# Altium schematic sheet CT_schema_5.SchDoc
size 422 x 414 mm
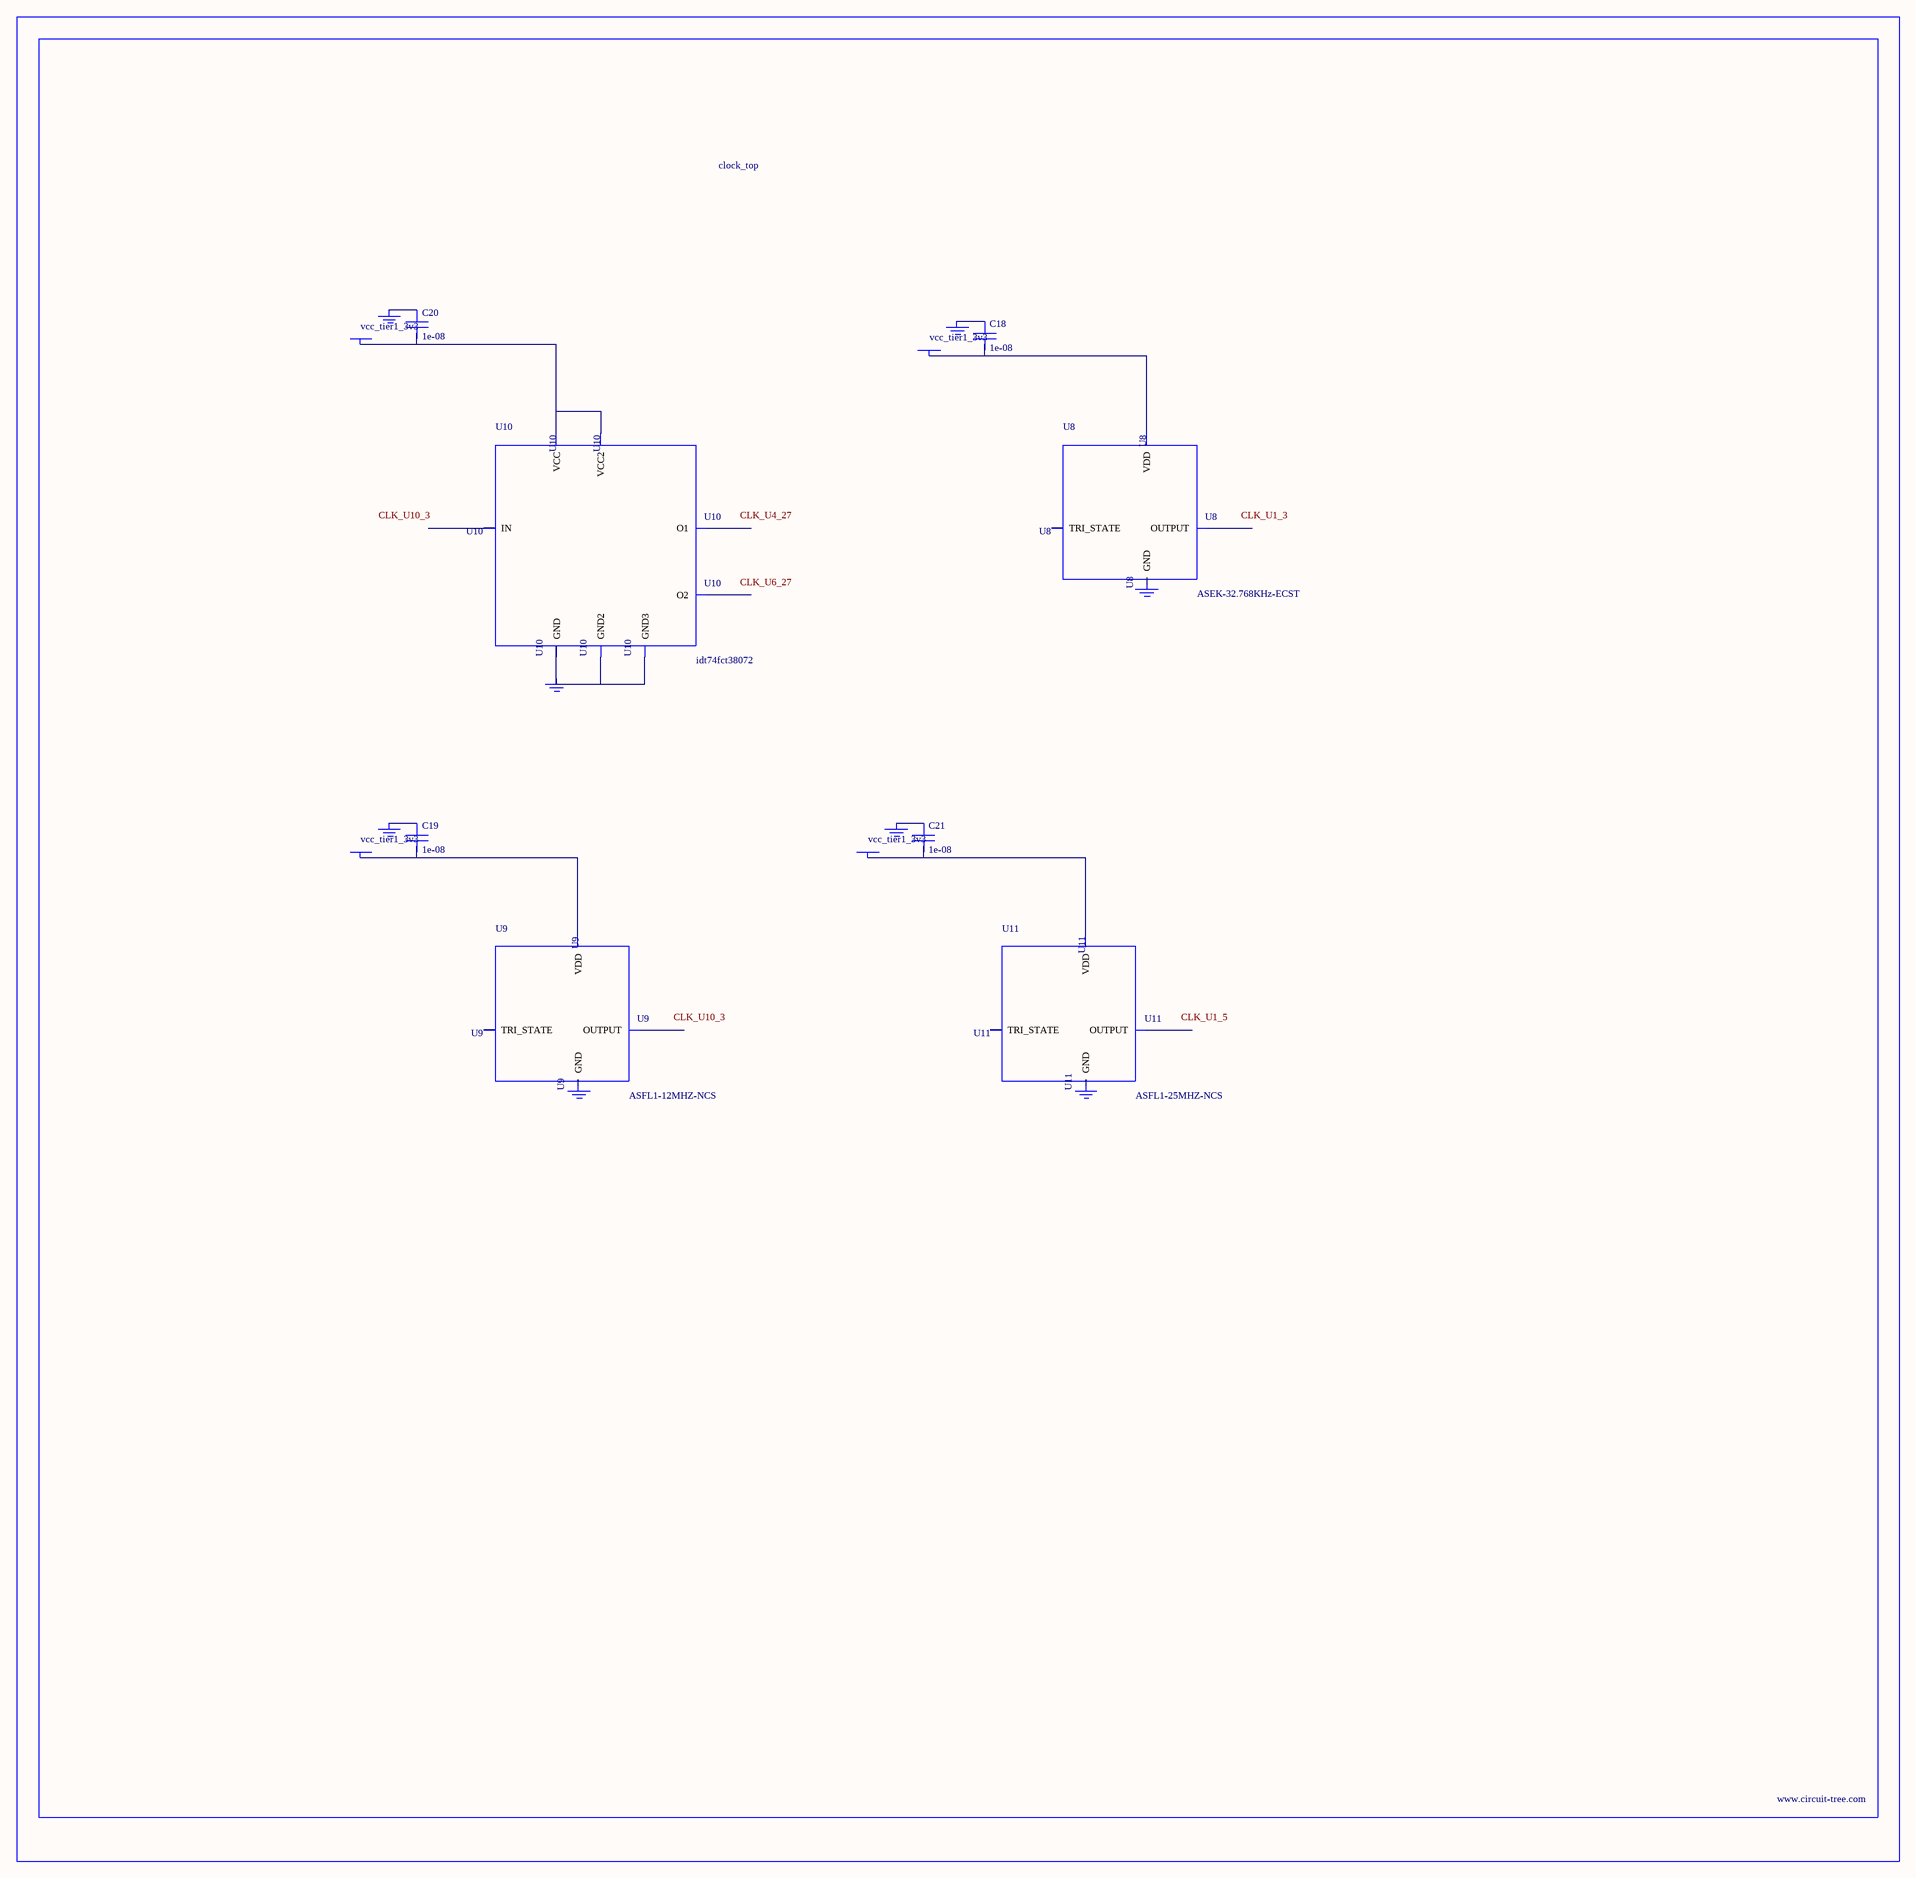
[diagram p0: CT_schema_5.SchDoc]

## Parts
BORDER4  (no value)
C18  1e-08  [C0402]
C19  1e-08  [C0402]
C20  1e-08  [C0402]
C21  1e-08  [C0402]
GND_INSTANCE_4_0  (no value)
GND_INSTANCE_4_1  (no value)
GND_INSTANCE_4_2  (no value)
GND_INSTANCE_4_3  (no value)
GND_INSTANCE_4_4  (no value)
GND_INSTANCE_4_5  (no value)
GND_INSTANCE_4_6  (no value)
GND_INSTANCE_4_7  (no value)
POWER_INSTANCE_4_0  vcc_tier1_3v3
POWER_INSTANCE_4_1  vcc_tier1_3v3
POWER_INSTANCE_4_2  vcc_tier1_3v3
POWER_INSTANCE_4_3  vcc_tier1_3v3
U8  ASEK-32.768KHz-ECST  [ASEK]
U9  ASFL1-12MHZ-NCS  [ASFL1]
U10  idt74fct38072  [IDT74FCT38072]
U11  ASFL1-25MHZ-NCS  [ASFL1]

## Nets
NetC18_1: C18.1 GND_INSTANCE_4_0.0(GND)
NetC18_2: C18.2 POWER_INSTANCE_4_0.0(PWR) U8.4(VDD)
NetC19_1: C19.1 GND_INSTANCE_4_2.0(GND)
NetC19_2: C19.2 POWER_INSTANCE_4_1.0(PWR) U9.4(VDD)
NetC20_1: C20.1 GND_INSTANCE_4_4.0(GND)
NetC20_2: C20.2 POWER_INSTANCE_4_2.0(PWR) U10.1(VCC) U10.2(VCC2)
NetC21_1: C21.1 GND_INSTANCE_4_6.0(GND)
NetC21_2: C21.2 POWER_INSTANCE_4_3.0(PWR) U11.4(VDD)
NetGND_INSTANCE_4_5_0: GND_INSTANCE_4_5.0(GND) U10.4(GND) U10.5(GND2) U10.8(GND3)

Not connected (* = marked no-connect by the designer): GND_INSTANCE_4_1 0(GND); GND_INSTANCE_4_3 0(GND); GND_INSTANCE_4_7 0(GND); U8 1(TRI_STATE) 2(GND) 3(OUTPUT); U9 1(TRI_STATE) 2(GND) 3(OUTPUT); U10 3(IN) 6(O2) 7(O1); U11 1(TRI_STATE) 2(GND) 3(OUTPUT)

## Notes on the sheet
- Labels drawn without touching a wire or pin: CLK_U1_3, CLK_U1_5, CLK_U4_27, CLK_U6_27, CLK_U10_3

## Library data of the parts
BORDER4 = BORDER_PAGE4
C18-C21 = C0402C103K3RAC
GND_INSTANCE_4_0-GND_INSTANCE_4_7 = GND
POWER_INSTANCE_4_0-POWER_INSTANCE_4_3 = PWR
